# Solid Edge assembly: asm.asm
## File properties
Author: Deepak Maini
Template: Normal.asm
Last saved by: CADCIM
Revision: 8
Application: Solid Edge
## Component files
plate.par
bolt.par
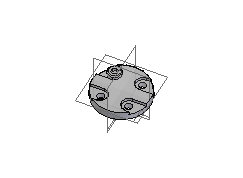
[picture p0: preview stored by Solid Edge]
